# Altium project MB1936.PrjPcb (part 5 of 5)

## Sheet Power_PMIC.SchDoc: Power PMIC
size A3; Date: Not used; ApprovedBy: Not used; CheckedBy: Not used; Author: Not used; CompanyName: STMicroelectronics; DrawnBy: Not used; Engineer: Not used; Organization: Not used; Address1: Not used; Address2: Not used; Address3: Not used; Address4: Not used; DocumentNumber: Not used; Revision: Not used; SheetNumber: 4; SheetTotal: 18
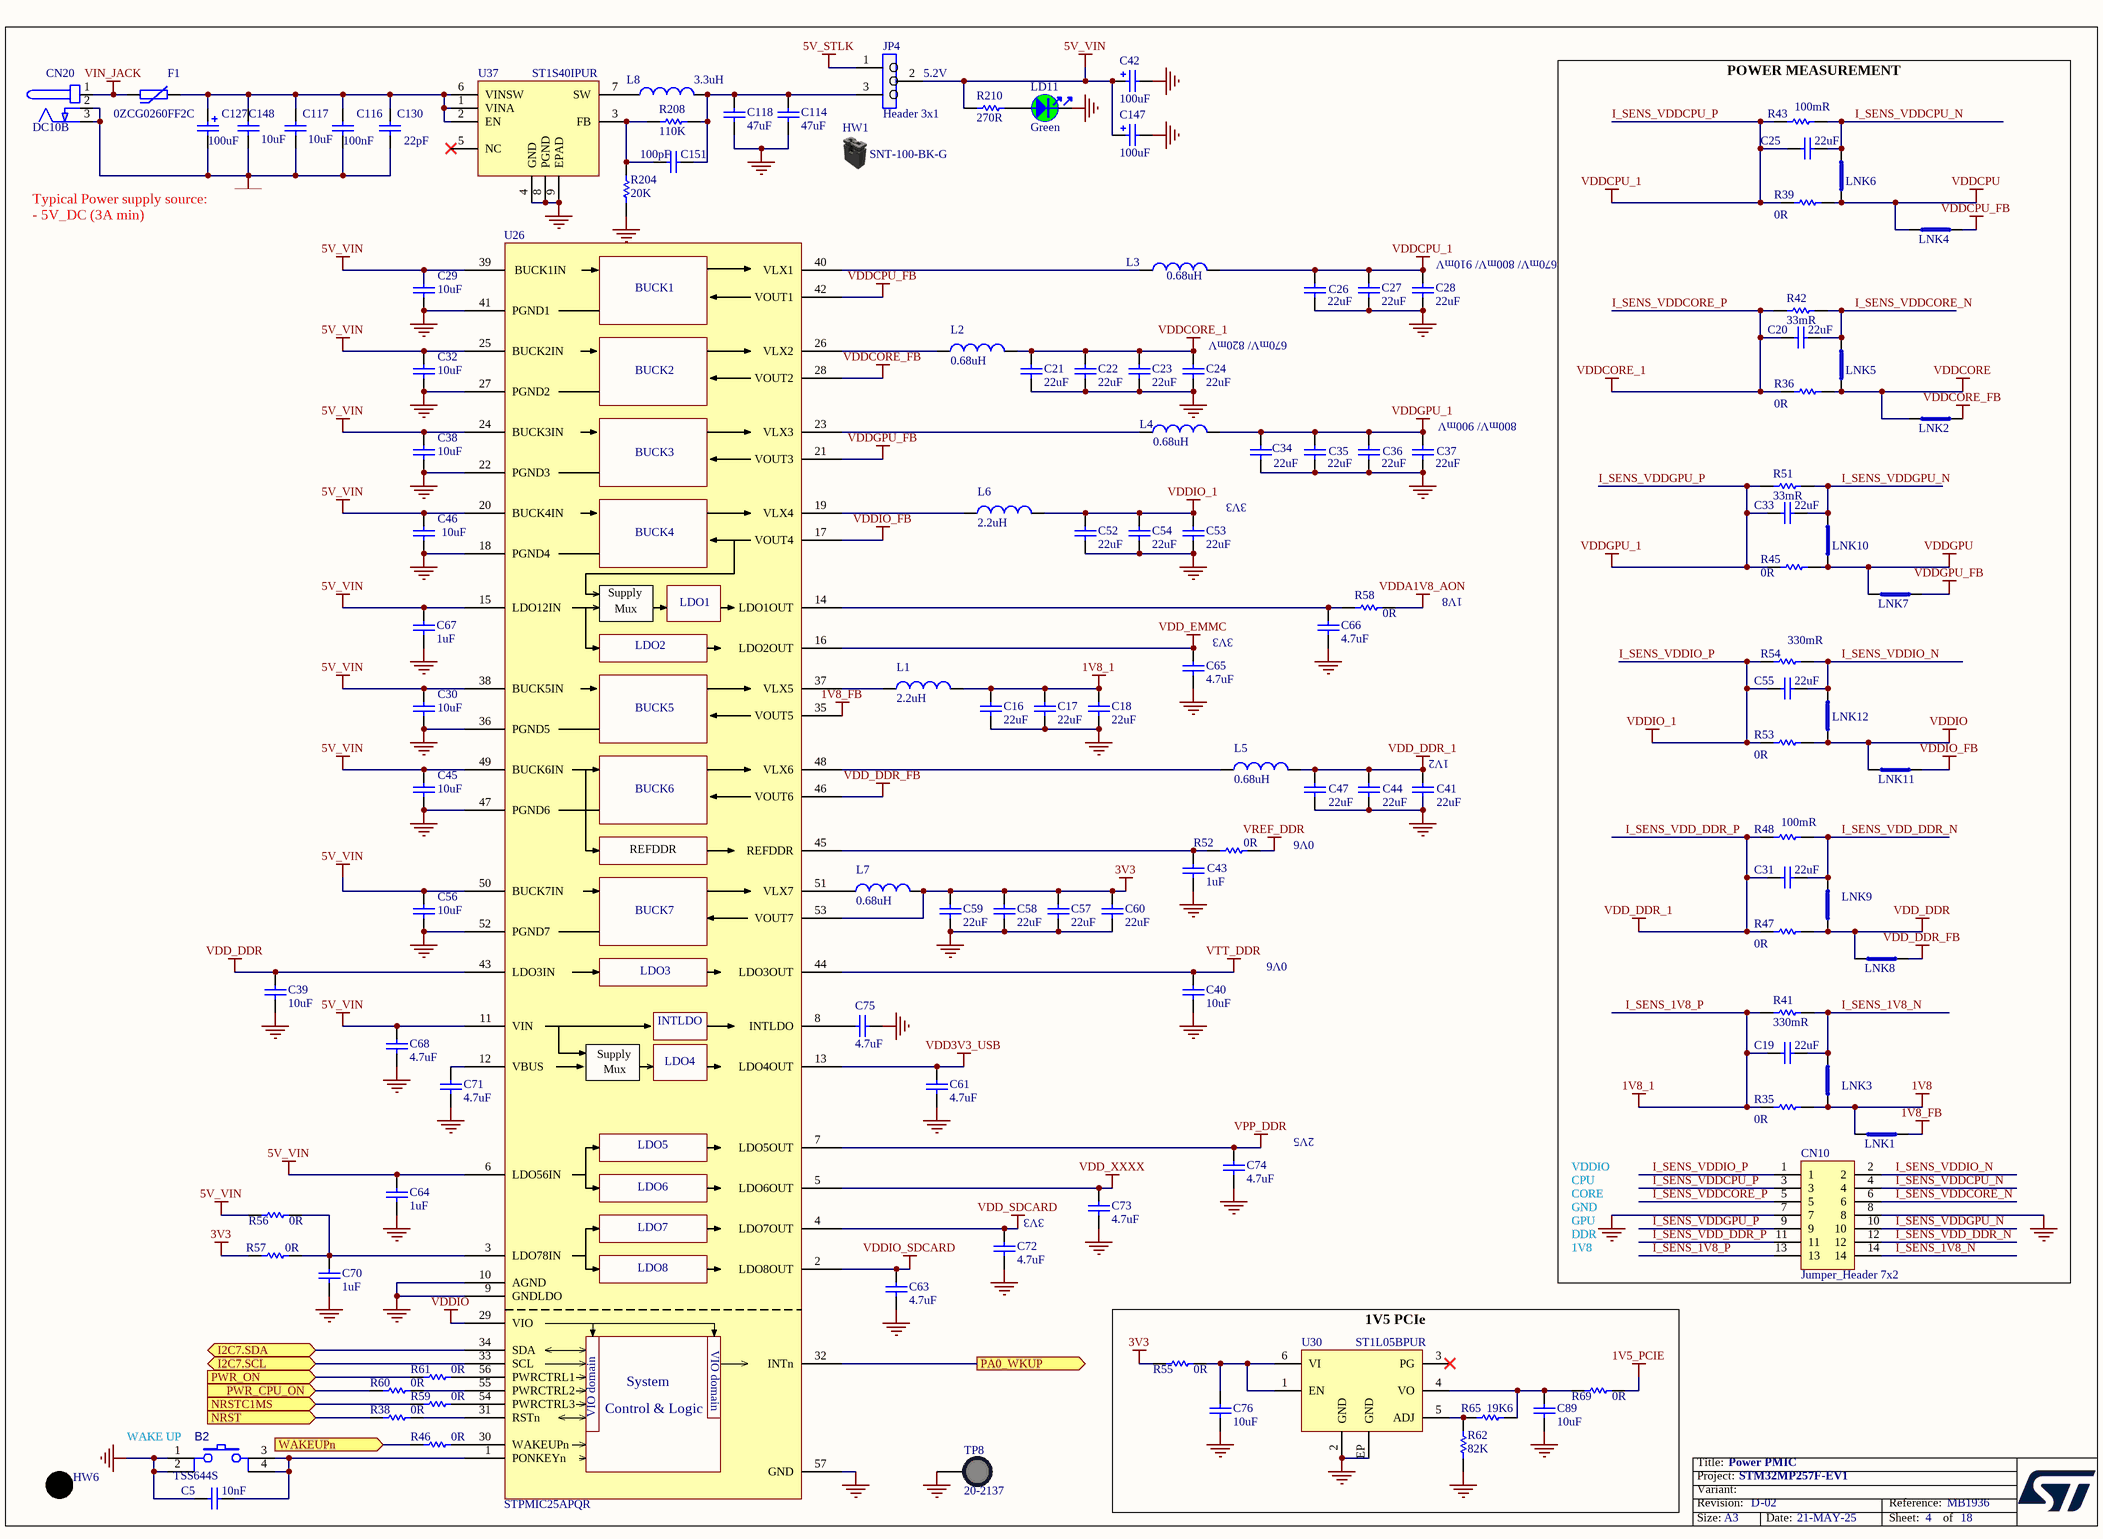
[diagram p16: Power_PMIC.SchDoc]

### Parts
B2  value TSS644S  [SWI_KNITTER_TSS644S]  (hidden comment: SW_PUSH_SMD)
C5  value 10nF  [C0402]  (hidden comment: Capacitor)
C16  value 22uF  [C0805]  (hidden comment: Capacitor)
C17  value 22uF  [C0805]  (hidden comment: Capacitor)
C18  value 22uF  [C0805]  (hidden comment: Capacitor)
C19  value 22uF  [C0603]  (hidden comment: Capacitor)
C20  value 22uF  [C0603]  (hidden comment: Capacitor)
C21  value 22uF  [C0603]  (hidden comment: Capacitor)
C22  value 22uF  [C0603]  (hidden comment: Capacitor)
C23  value 22uF  [C0603]  (hidden comment: Capacitor)
C24  value 22uF  [C0603]  (hidden comment: Capacitor)
C25  value 22uF  [C0603]  (hidden comment: Capacitor)
C26  value 22uF  [C0603]  (hidden comment: Capacitor)
C27  value 22uF  [C0603]  (hidden comment: Capacitor)
C28  value 22uF  [C0603]  (hidden comment: Capacitor)
C29  value 10uF  [C0603]  (hidden comment: Capacitor)
C30  value 10uF  [C0603]  (hidden comment: Capacitor)
C31  value 22uF  [C0603]  (hidden comment: Capacitor)
C32  value 10uF  [C0603]  (hidden comment: Capacitor)
C33  value 22uF  [C0603]  (hidden comment: Capacitor)
C34  value 22uF  [C0603]  (hidden comment: Capacitor)
C35  value 22uF  [C0603]  (hidden comment: Capacitor)
C36  value 22uF  [C0603]  (hidden comment: Capacitor)
C37  value 22uF  [C0603]  (hidden comment: Capacitor)
C38  value 10uF  [C0603]  (hidden comment: Capacitor)
C39  value 10uF  [C0402]  (hidden comment: Capacitor)
C40  value 10uF  [C0402]  (hidden comment: Capacitor)
C41  value 22uF  [C0603]  (hidden comment: Capacitor)
C42  value 100uF  [CPOL_TCJ-B_1210_H210]  (hidden comment: Cap_POL_TANA)
C43  value 1uF  [C0402]  (hidden comment: Capacitor)
C44  value 22uF  [C0603]  (hidden comment: Capacitor)
C45  value 10uF  [C0603]  (hidden comment: Capacitor)
C46  value 10uF  [C0603]  (hidden comment: Capacitor)
C47  value 22uF  [C0603]  (hidden comment: Capacitor)
C52  value 22uF  [C0805]  (hidden comment: Capacitor)
C53  value 22uF  [C0805]  (hidden comment: Capacitor)
C54  value 22uF  [C0805]  (hidden comment: Capacitor)
C55  value 22uF  [C0603]  (hidden comment: Capacitor)
C56  value 10uF  [C0603]  (hidden comment: Capacitor)
C57  value 22uF  [C0805]  (hidden comment: Capacitor)
C58  value 22uF  [C0805]  (hidden comment: Capacitor)
C59  value 22uF  [C0805]  (hidden comment: Capacitor)
C60  value 22uF  [C0805]  (hidden comment: Capacitor)
C61  value 4.7uF  [C0402]  (hidden comment: Capacitor)
C63  value 4.7uF  [C0402]  (hidden comment: Capacitor)
C64  value 1uF  [C0402]  (hidden comment: Capacitor)
C65  value 4.7uF  [C0402]  (hidden comment: Capacitor)
C66  value 4.7uF  [C0402]  (hidden comment: Capacitor)
C67  value 1uF  [C0402]  (hidden comment: Capacitor)
C68  value 4.7uF  [C0402]  (hidden comment: Capacitor)
C70  value 1uF  [C0402]  (hidden comment: Capacitor)
C71  value 4.7uF  [C0603]  (hidden comment: Capacitor)
C72  value 4.7uF  [C0402]  (hidden comment: Capacitor)
C73  value 4.7uF  [C0402]  (hidden comment: Capacitor)
C74  value 4.7uF  [C0402]  (hidden comment: Capacitor)
C75  value 4.7uF  [C0402]  (hidden comment: Capacitor)
C76  value 10uF  [C0603]  (hidden comment: Capacitor)
C89  value 10uF  [C0603]  (hidden comment: Capacitor)
C114  value 47uF  [C0805]  (hidden comment: Capacitor)
C116  value 100nF  [C0805_H0P85]  (hidden comment: Capacitor)
C117  value 10uF  [C0805]  (hidden comment: Capacitor)
C118  value 47uF  [C0805]  (hidden comment: Capacitor)
C127  value 100uF  [CPOL_WURTH_WCAP-ASLL_8X10P5]  (hidden comment: Cap_POL_TANA)
C130  value 22pF  [C0402]  (hidden comment: Capacitor)
C147  value 100uF  [CPOL_TCJ-B_1210_H210]  (hidden comment: Cap_POL_TANA)
C148  value 10uF  [C0805]  (hidden comment: Capacitor)
C151  value 100pF  [C0402]  (hidden comment: Capacitor)
CN10  value Jumper_Header 7x2  [CON_SAMTEC_TSW-107-07-X-D]  (hidden comment: Header 7x2)
CN20  DC10B  [CON_DC-POWER-SOCKET_CLIFF_FC68149_DC10B]
F1  0ZCG0260FF2C  [PTC_BEL-FUSE_1812_0ZCG0260FF2C]
HW1  value SNT-100-BK-G  (hidden comment: Shunt Black 2.54mm)  (mechanical)
HW6  SW-CAP-KTSC-62K  (value not drawn)  (mechanical)
JP4  value Header 3x1  [CON_SAMTEC_TSW-103-07-F-S]  (hidden comment: Jumper_Header 3x1)
L1  value 2.2uH  [IND_2016_MURATA_LQM2MPN2R2NG0]  (hidden comment: Inductor)
L2  value 0.68uH  [IND_2520_TOKO_DFE252012P]  (hidden comment: Inductor)
L3  value 0.68uH  [IND_2016_MURATA_LQM2MPN2R2NG0]  (hidden comment: Inductor)
L4  value 0.68uH  [IND_2520_TOKO_DFE252012P]  (hidden comment: Inductor)
L5  value 0.68uH  [IND_2016_MURATA_LQM2MPN2R2NG0]  (hidden comment: Inductor)
L6  value 2.2uH  [IND_2016_MURATA_LQM2MPN2R2NG0]  (hidden comment: Inductor)
L7  value 0.68uH  [IND_2016_MURATA_LQM2MPN2R2NG0]  (hidden comment: Inductor)
L8  value 3.3uH  [IND_5040_WURTH_74404054033]  (hidden comment: Inductor)
LD11  value Green  [LED_0603_OSRAM_LG-Q396-PS-35_GREEN_1A2K_H0P4]  (hidden comment: LED_green)
LNK1  link_200  [LINK200]  (value not drawn)  (no BOM)
LNK2  link_200  [LINK200]  (value not drawn)  (no BOM)
LNK3  link_200  [LINK200]  (value not drawn)  (no BOM)
LNK4  link_200  [LINK200]  (value not drawn)  (no BOM)
LNK5  link_200  [LINK200]  (value not drawn)  (no BOM)
LNK6  link_200  [LINK200]  (value not drawn)  (no BOM)
LNK7  link_200  [LINK200]  (value not drawn)  (no BOM)
LNK8  link_200  [LINK200]  (value not drawn)  (no BOM)
LNK9  link_200  [LINK200]  (value not drawn)  (no BOM)
LNK10  link_200  [LINK200]  (value not drawn)  (no BOM)
LNK11  link_200  [LINK200]  (value not drawn)  (no BOM)
LNK12  link_200  [LINK200]  (value not drawn)  (no BOM)
R35  value 0R  [R0603]  (hidden comment: Resistor)
R36  value 0R  [R0603]  (hidden comment: Resistor)
R38  value 0R  [R0402]
R39  value 0R  [R0603]  (hidden comment: Resistor)
R41  value 330mR  [R0603]  (hidden comment: Resistor)
R42  value 33mR  [R0603]  (hidden comment: Resistor)
R43  value 100mR  [R0603]  (hidden comment: Resistor)
R45  value 0R  [R0603]  (hidden comment: Resistor)
R46  value 0R  [R0402]
R47  value 0R  [R0603]  (hidden comment: Resistor)
R48  value 100mR  [R0603]  (hidden comment: Resistor)
R51  value 33mR  [R0603]  (hidden comment: Resistor)
R52  value 0R  [R0402]  (hidden comment: Resistor)
R53  value 0R  [R0603]  (hidden comment: Resistor)
R54  value 330mR  [R0603]  (hidden comment: Resistor)
R55  value 0R  [R0603]  (hidden comment: Resistor)
R56  value 0R  [R0603]  (hidden comment: Resistor)
R57  value 0R  [R0402]  (hidden comment: Resistor)
R58  value 0R  [R0603]  (hidden comment: Resistor)
R59  value 0R  [R0402]
R60  value 0R  [R0402]
R61  value 0R  [R0402]
R62  value 82K  [R0402]  (hidden comment: Resistor)
R65  value 19K6  [R0402]  (hidden comment: Resistor)
R69  value 0R  [R0603]  (hidden comment: Resistor)
R204  value 20K  [R0402]  (hidden comment: Resistor)
R208  value 110K  [R0402]  (hidden comment: Resistor)
R210  value 270R  [R0402]  (hidden comment: Resistor)
TP8  value 20-2137  [TP_PTH-1P02MM_TEST-TERMINAL_RS_101-2391_BLACK]  (hidden comment: Test_pin_conn_black)
U26  value STPMIC25APQR  [ICC_QFN56-EPAD_6P5X6P5_P040]  (hidden comment: STPMIC2)
U30  ST1L05BPUR  [ICC_DFN6-EPAD_3X3_P095]
U37  ST1S40IPUR  [ICC_VFQFPN8-EPAD_4X4_P080]

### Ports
I2C7.SCL (bidir), I2C7.SDA (bidir), NRST (in), NRSTC1MS (in), PA0_WKUP (out), PWR_CPU_ON (in), PWR_ON (in), WAKEUPn (in)

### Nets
1V5_PCIE: R69.2
1V8: LNK1.2 LNK3.2 R35.2
1V8_FB: LNK1.1 U26.35(VOUT5)
3V3: C57.2 C58.2 C59.2 C60.2 L7.2 R55.1 R57.1 U26.53(VOUT7)
5V_STLK: JP4.1
5V_VIN: C29.2 C30.2 C32.2 C38.2 C42.1 C45.2 C46.2 C56.2 C64.2 C67.2 C68.2 C147.1 JP4.2 R56.1 R210.2 U26.6(LDO56IN) U26.11(VIN) U26.15(LDO12IN) U26.20(BUCK4IN) U26.24(BUCK3IN) U26.25(BUCK2IN) U26.38(BUCK5IN) U26.39(BUCK1IN) U26.49(BUCK6IN) U26.50(BUCK7IN)
GND: B2.1 B2.2 C5.1 C16.1 C17.1 C18.1 C21.1 C22.1 C23.1 C24.1 C26.1 C27.1 C28.1 C29.1 C30.1 C32.1 C34.1 C35.1 C36.1 C37.1 C38.1 C39.1 C40.1 C41.1 C42.2 C43.2 C44.1 C45.1 C46.1 C47.1 C52.1 C53.1 C54.1 C56.1 C57.1 C58.1 C59.1 C60.1 C61.1 C63.2 C64.1 C65.2 C66.1 C67.1 C68.1 C70.1 C71.1 C72.2 C73.2 C74.2 C75.2 C76.1 C89.1 C114.1 C116.1 C117.1 C118.1 C127.2 C130.1 C147.2 C148.1 CN10.7 CN10.8 CN20.2 CN20.3 LD11.2 R62.1 R204.1 TP8.1 U26.9(GNDLDO) U26.10(AGND) U26.18(PGND4) U26.22(PGND3) U26.27(PGND2) U26.36(PGND5) U26.41(PGND1) U26.47(PGND6) U26.52(PGND7) U26.57(GND) U30.2(GND) U30.EP(GND) U37.4(GND) U37.8(PGND) U37.9(EPAD)
I_SENS_1V8_P: C16.2 C17.2 C18.2 C19.2 CN10.13 L1.2 R35.1 R41.1  [also labelled 1V8_1]
I_SENS_VDD_DDR_P: C31.2 C41.2 C44.2 C47.2 CN10.11 L5.2 R47.1 R48.1  [also labelled VDD_DDR_1]
I_SENS_VDDCORE_P: C20.2 C21.2 C22.2 C23.2 C24.2 CN10.5 L2.2 R36.1 R42.1  [also labelled VDDCORE_1]
I_SENS_VDDCPU_P: C25.2 C26.2 C27.2 C28.2 CN10.3 L3.2 R39.1 R43.1  [also labelled VDDCPU_1]
I_SENS_VDDGPU_P: C33.2 C34.2 C35.2 C36.2 C37.2 CN10.9 L4.2 R45.1 R51.1  [also labelled VDDGPU_1]
I_SENS_VDDIO_P: C52.2 C53.2 C54.2 C55.2 CN10.1 L6.2 R53.1 R54.1  [also labelled VDDIO_1]
VDD3V3_USB: C61.2 U26.13(LDO4OUT)
VDD_DDR: C39.2 LNK8.2 LNK9.2 R47.2 U26.43(LDO3IN)
VDD_DDR_FB: LNK8.1 U26.46(VOUT6)
VDD_EMMC: C65.1 U26.16(LDO2OUT)
VDD_SDCARD: C72.1 U26.4(LDO7OUT)
VDD_XXXX: C73.1 U26.5(LDO6OUT)
VDDA1V8_AON: R58.2
VDDCORE: LNK2.2 LNK5.1 R36.2
VDDCORE_FB: LNK2.1 U26.28(VOUT2)
VDDCPU: LNK4.1 LNK6.1 R39.2
VDDCPU_FB: LNK4.2 U26.42(VOUT1)
VDDGPU: LNK7.2 LNK10.1 R45.2
VDDGPU_FB: LNK7.1 U26.21(VOUT3)
VDDIO: LNK11.2 LNK12.2 R53.2 U26.29(VIO)
VDDIO_FB: LNK11.1 U26.17(VOUT4)
VDDIO_SDCARD: C63.1 U26.2(LDO8OUT)
VIN_JACK: CN20.1 F1.1
VPP_DDR: C74.1 U26.7(LDO5OUT)
VREF_DDR: R52.2
VTT_DDR: C40.2 U26.44(LDO3OUT)
I2C7.SCL: U26.33(SCL) ; port I2C7.SCL
I2C7.SDA: U26.34(SDA) ; port I2C7.SDA
I_SENS_1V8_N: C19.1 CN10.14 LNK3.1 R41.2
I_SENS_VDD_DDR_N: C31.1 CN10.12 LNK9.1 R48.2
I_SENS_VDDCORE_N: C20.1 CN10.6 LNK5.2 R42.2
I_SENS_VDDCPU_N: C25.1 CN10.4 LNK6.2 R43.2
I_SENS_VDDGPU_N: C33.1 CN10.10 LNK10.2 R51.2
I_SENS_VDDIO_N: C55.1 CN10.2 LNK12.1 R54.2
NRST: R38.1 ; port NRST
NRSTC1MS: R59.1 ; port NRSTC1MS
PA0_WKUP: U26.32(INTn) ; port PA0_WKUP
PWR_CPU_ON: R60.1 ; port PWR_CPU_ON
PWR_ON: R61.1 ; port PWR_ON
WAKEUPn: R46.1 ; port WAKEUPn
NetB2_3: B2.3 B2.4 C5.2 U26.1(PONKEYn)
NetC43_1: C43.1 R52.1 U26.45(REFDDR)
NetC66_2: C66.2 R58.1 U26.14(LDO1OUT)
NetC70_2: C70.2 R56.2 R57.2 U26.3(LDO78IN)
NetC71_2: C71.2 U26.12(VBUS)
NetC75_1: C75.1 U26.8(INTLDO)
NetC76_2: C76.2 R55.2 U30.1(EN) U30.6(VI)
NetC89_2: C89.2 R65.2 R69.1 U30.4(VO)
NetC114_2: C114.2 C118.2 C151.1 JP4.3 L8.2 R208.1
NetC116_2: C116.2 C117.2 C127.1 C130.2 C148.2 F1.2 U37.1(VINA) U37.2(EN) U37.6(VINSW)
NetC151_2: C151.2 R204.2 R208.2 U37.3(FB)
NetL1_1: L1.1 U26.37(VLX5)
NetL2_1: L2.1 U26.26(VLX2)
NetL3_1: L3.1 U26.40(VLX1)
NetL4_1: L4.1 U26.23(VLX3)
NetL5_1: L5.1 U26.48(VLX6)
NetL6_1: L6.1 U26.19(VLX4)
NetL7_1: L7.1 U26.51(VLX7)
NetL8_1: L8.1 U37.7(SW)
NetLD11_1: LD11.1 R210.1
NetR38_2: R38.2 U26.31(RSTn)
NetR46_2: R46.2 U26.30(WAKEUPn)
NetR59_2: R59.2 U26.54(PWRCTRL3)
NetR60_2: R60.2 U26.55(PWRCTRL2)
NetR61_2: R61.2 U26.56(PWRCTRL1)
NetR62_2: R62.2 R65.1 U30.5(ADJ)

Not connected (* = marked no-connect by the designer): U30 3(PG)*; U37 5(NC)*

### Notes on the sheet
- 5.2V
- Typical Power supply source:
  - 5V_DC (3A min)
- (near C28) 670mV/ 800mV/ 910mV
- (near C24) 670mV/ 820mV
- (near C37) 800mV/ 900mV
- 3V3
- 1V8
- (near C65) 3V3
- (near C41) 1V2
- 0V6
- 2V5
- (near C72) 3V3
- VDDIO
- CPU
- GND
- CORE
- POWER MEASUREMENT
- DDR
- GPU
- (near B2) WAKE UP
- 1V5 PCIe

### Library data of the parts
B2 = MCD-02417: Push Button, NO, 0.05A, 12V, 2.6N, SMD, 9.0x6.2mm, T=7.3mm, changeable caps KTSC-6xx; Part_Type: Misc; Manufacturer: KNITTER-SWITCH; Part_Preference: Recommended; Manufacturer_HQ_COO: Unknown; Component_Country_Of_Origin: China; ShowFields: YES; ID: 4523
C5 = MCD-02198: Capacitor, MLCC, 10nF, 50V, X7R, +/-10%, 0402, T=0.5mm; Manufacturer_Part_Number: CC0402KRX7R9BB103; Manufacturer: YAGEO; Part_Preference: Recommended; Order_Code_RS: 6169644; Component_Country_Of_Origin: China; ShowFields: YES; ID: 4298
C16-C18 C52-C54 C57-C60 = MCD-03139: Capacitor, MLCC, 22uF, 10V, X5R, +/-20%, 0805, T=1,25mm; Part_Preference: Recommended; Manufacturer: MURATA; Manufacturer_Part_Number: GRM21BR61A226ME51; ShowFields: YES; ID: 5255; Component_Country_Of_Origin: China, Japan
C19 C20 C22-C26 C31 C33-C37 C41 C44 C47 C55 = MCD-00100: Capacitor, MLCC, 22uF, 6V3, X5R, +/-20%, 0603, T=0,8mm; Manufacturer_Part_Number: GRM188R60J226MEA0; Manufacturer: MURATA; Part_Preference: Recommended; Partial_Alternate_Internal_Part_Number: MCD-04184; Component_Country_Of_Origin: Japan°°; ID: 2766; ShowFields: YES
C21 C27 C28 = MCD-00100: Capacitor, MLCC, 22uF, 6V3, X5R, +/-20%, 0603, T=0,8mm; Part_Preference: Recommended; Manufacturer: MURATA; Manufacturer_Part_Number: GRM188R60J226MEA0; Partial_Alternate_Internal_Part_Number: MCD-04184; Component_Country_Of_Origin: Japan°°; ID: 2766; ShowFields: YES
C29 C30 C32 C38 C45 C46 C56 = MCD-00099: Capacitor, MLCC, 10uF, 10V, X5R, +/-10%, 0603, T=0,8mm; Manufacturer_Part_Number: GRM188R61A106KE69; Manufacturer: MURATA; Part_Preference: Recommended; Partial_Alternate_Internal_Part_Number: MCD-03152; Order_Code_RS: 2494233; Component_Country_Of_Origin: Japan°°; ID: 2770; ShowFields: YES
C39 C40 = MCD-03140: Capacitor, MLCC, 10uF, 6.3V, X5R, +/-20%, 0402, T=0.5mm; Part_Preference: Recommended; Manufacturer: MURATA; Manufacturer_Part_Number: GRM155R60J106ME05; ShowFields: YES; ID: 5256; Component_Country_Of_Origin: China, Japan
C42 C147 = MCD-01796: Capacitor, Tantalum, 100uF, 6V3, 40mR, +/-20%,  Type_B (3528 metric), T=1.9mm; Part_Preference: Recommended; Manufacturer: AVX; Manufacturer_Part_Number: TCJB107M006R0040; Partial_Alternate_Internal_Part_Number: MCD-04209; Component_Country_Of_Origin: Czech Republic; ShowFields: YES; ID: 3896
C43 = MCD-01722: Capacitor, MLCC, 1uF, 10V, X5R, +/-10%, 0402, T=0.5mm; Part_Preference: Recommended; Manufacturer: YAGEO; Manufacturer_Part_Number: CC0402KRX5R6BB105; Component_Country_Of_Origin: China; ID: 3822; ShowFields: YES
C61 C63 C65 C66 C68 C72-C75 = MCD-01356: Capacitor, MLCC, 4.7uF, 6V3, X5R, +/-20%, 0402, T=0.5mm; Manufacturer_Part_Number: GRM155R60J475ME47; Manufacturer: MURATA; Part_Preference: Recommended; Partial_Alternate_Internal_Part_Number: MCD-04455; Order_Code_RS: 814-5230; Component_Country_Of_Origin: Japan°°; ShowFields: YES; ID: 3456
C64 C67 C70 = MCD-00095: Capacitor, MLCC, 1uF, 25V, X5R, +/-10%, 0402, T=0.5mm; Part_Preference: Recommended; Manufacturer: MURATA; Manufacturer_Part_Number: GRM155R61E105KA12; Partial_Alternate_Internal_Part_Number: MCD-04188; Order_Code_RS: 2218855; Component_Country_Of_Origin: Japan°°; ShowFields: YES; ID: 2772
C71 = MCD-00097: Capacitor, MLCC, 4.7uF, 16V, X5R, +/-20%, 0603, T=0.8mm; Part_Preference: Recommended; Manufacturer: MURATA; Manufacturer_Part_Number: GRM188R61C475KE11; Component_Country_Of_Origin: Japan°°; ShowFields: YES; ID: 2767
C76 C89 = MCD-00099: Capacitor, MLCC, 10uF, 10V, X5R, +/-10%, 0603, T=0.8mm; Part_Preference: Recommended; Manufacturer: MURATA; Manufacturer_Part_Number: GRM188R61A106KE69; Partial_Alternate_Internal_Part_Number: MCD-03152; Order_Code_RS: 2494233; Component_Country_Of_Origin: Japan°°; ShowFields: YES; ID: 2770
C114 C118 = MCD-00204: Capacitor, MLCC, 47uF, 10V, X5R, +/-20%, 0805, T=1,25mm; Part_Preference: Recommended; Manufacturer: MURATA; Manufacturer_Part_Number: GRM21BR61A476ME15; Component_Country_Of_Origin: Japan°°; ID: 2664; ShowFields: YES
C116 = MCD-01525: Capacitor, MLCC, 100nF, 50V, X7R, 10%, 0805, T=0,85mm; BMS_Part_Number: 9142249; Part_Preference: Recommended; Manufacturer: YAGEO; Manufacturer_Part_Number: CC0805KRX7R9BB104; Order_Code_RS: 669-8842; Component_Country_Of_Origin: China; ID: 3625; ShowFields: YES
C117 C148 = MCD-00014: Capacitor, MLCC, 10uF, 25V, X5R, +/-10%, 0805, T=0,85mm; Part_Preference: Recommended; Manufacturer: YAGEO; Manufacturer_Part_Number: CC0805KRX5R8BB106; Full_Alternate_Internal_Part_Number: MCD-02385; Partial_Alternate_Internal_Part_Number: MCD-03053; Component_Country_Of_Origin: China; ID: 2468; ShowFields: YES
C127 = MCD-01683: Capacitor,Electrolytic,100uF,35V, 20%, SMT, D=8mm, T=10.5mm; Part_Preference: Recommended; Manufacturer: WURTH ELEKTRONIK; Manufacturer_Part_Number: 865060553006; Order_Code_RS: 839-5753; Component_Country_Of_Origin: Unknown; ID: 3783; ShowFields: YES
C130 = MCD-01995: Capacitor, MLCC, 22pF, 50V, C0G, 5%, 0402, T=0,5mm; Part_Preference: Recommended; Manufacturer: TDK; Manufacturer_Part_Number: C1005NP01H220J050BA; Partial_Alternate_Internal_Part_Number: MCD-04601; Component_Country_Of_Origin: Unknown; ID: 4095; ShowFields: YES
C151 = MCD-00205: Capacitor,MLCC,100pF,50V,NPO,+/-5%,0402,T=0,5mm; Manufacturer_Part_Number: CC0402JRNPO9BN101; Manufacturer: YAGEO; Part_Preference: Recommended; Fitted: YES; Component_Country_Of_Origin: China; ID: 2658
CN10 = MCD-02123: Header, 7x2, 2,54mm, VR, TH, Height 5.84mm/2.54mm; Part_Type: Connector; Part_Preference: Recommended; Manufacturer: SAMTEC; Manufacturer_Part_Number: TSW-107-07-G-D; Partial_Alternate_Internal_Part_Number: MCD-04207, MCD-04247; Component_Country_Of_Origin: China, Costa Rica, Malaysia, USA, Vietnam; ID: 4223; ShowFields: YES
CN20 = MCD-00173: DC-Power-Jack, 2.5mm, 5A, RA, TH; BMS_Part_Number: 9087803; Part_Preference: Recommended; Part_Type: Connector; Manufacturer: CLIFF; Partial_Alternate_Internal_Part_Number: MCD-04205, MCD-04592; Value: Jack_DC-Power_DC10B; Component_Country_Of_Origin: Taiwan; ID: 2695; ShowFields: YES
F1 = MCD-00624: SMD, PTC resettable fuse, IH:2.6A, IT:5A, Vdc_max:8V, Rmax:47mohm, BELFUSE; Part_Preference: Recommended; Part_Type: Misc; Component_Country_Of_Origin: Unknown; ID: 3118; ShowFields: YES
HW1 = MCD-00043: SHUNT 2.54mm BLACK; Part_Type: Misc; Part_Preference: Recommended; Manufacturer: SAMTEC; Manufacturer_HQ_COO: Unknown; Partial_Alternate_Internal_Part_Number: MCD-01849, MCD-01864, MCD-02388, MCD-03991, MCD-04284, MCD-04580; Component_Country_Of_Origin: China, Costa Rica, Malaysia, USA, Vietnam; ShowFields: YES; ID: 2551; Alternate_EMS: A; Order_Code_RS: 158-7784
HW6 = MCD-02420: Black round cap for TSS6x series; Part_Type: Mechanical; Part_Preference: Recommended; Manufacturer: KNITTER-SWITCH; Manufacturer_HQ_COO: Unknown; Partial_Alternate_Internal_Part_Number: MCD-02526; Component_Country_Of_Origin: China; ID: 4526; ShowFields: YES; Alternate_EMS: M
JP4 = MCD-00111: Header, 3x1, 2.54mm, VR, TH, T=5.84mm/2.54mm; Part_Type: Connector; Part_Preference: Recommended; Manufacturer: SAMTEC; Manufacturer_Part_Number: TSW-103-07-F-S; Partial_Alternate_Internal_Part_Number: MCD-04583; Order_Code_RS: 161-2248; Component_Country_Of_Origin: China, Costa Rica, Malaysia, USA, Vietnam; ShowFields: YES; ID: 2760
L1 L6 = MCD-03143: Inductor, 2.2uH, +/-20%, Itemp= 1700mA, Isat= 2400mA, 0R140, 0806, T=1mm; Part_Preference: Recommended; Manufacturer: MURATA; Manufacturer_Part_Number: DFE201610E-2R2M=P2; ShowFields: YES; ID: 5259; Component_Country_Of_Origin: Vietnam
L2 L4 = MCD-03142: Inductor, 0.68uH, +/-20%, Itemp= 3900mA, Isat= 5400mA, 0R031, 1008, T=1.2mm; Part_Preference: Recommended; Manufacturer: MURATA; Manufacturer_Part_Number: DFE252012F-R68M=P2; ShowFields: YES; ID: 5258; Component_Country_Of_Origin: Vietnam
L3 L5 L7 = MCD-03141: Inductor, 0.68uH, +/-20%, Itemp= 3100mA, Isat= 4300mA, 0R043, 0806, T=1mm; Part_Preference: Recommended; Manufacturer: MURATA; Manufacturer_Part_Number: DFE201610E-R68M=P2; ShowFields: YES; ID: 5257; Component_Country_Of_Origin: Vietnam
L8 = MCD-02220: Fixed Inductors WE-LQS 5040 3.3uH 3.4A 24mOhm; Part_Preference: Recommended; Manufacturer: WURTH ELEKTRONIK; Manufacturer_Part_Number: 74404054033; Order_Code_RS: 814-2571; Component_Country_Of_Origin: Unknown; ID: 4320; ShowFields: YES
LD11 = MCD-02901: LED, Green, 2V, 20mA, 0603; Part_Type: Display; Part_Preference: Recommended; Manufacturer: EVERLIGHT; Manufacturer_Part_Number: 19-217/G7C-AN1P2/6T; Partial_Alternate_Internal_Part_Number: MCD-02400, MCD-00588; Component_Country_Of_Origin: China; ShowFields: YES; ID: 5017
LNK1-LNK12 = link_200: link 0.2mm
R35 R36 R39 R45 R47 R53 = MCD-00181: Resistor,0R,0603,ULO; Manufacturer_Part_Number: PMR03EZPJ000; Manufacturer: ROHM SEMICONDUCTOR; Part_Preference: Recommended; Provided_By: SUBCO; Component_Country_Of_Origin: Philippines, Thailand°°; ID: 2691; ShowFields: YES
R38 R46 R59-R61 = MCD-00052: Resistor,0R,0402,5%,1/16W; Manufacturer_Part_Number: RC0402JR-070RL; Manufacturer: YAGEO; Part_Preference: Recommended; ECCN_US: EAR99; ECCN_EU: NEC; Provided_By: SUBCO; Initial_Board_Reference: mb1274; Order_Code_RS: 9232516RL; Component_Country_Of_Origin: China; ID: 2540; ShowFields: YES
R41 R54 = MCD-03197: Resistor, 330mR, 0603, +/-1%, 1/5W; Part_Preference: Recommended; Manufacturer: YAGEO; Manufacturer_Part_Number: PT0603FR-7W0R33L; Partial_Alternate_Internal_Part_Number: MCD-04231; ShowFields: YES; ID: 5313; Component_Country_Of_Origin: Taiwan
R42 R51 = MCD-03229: Resistor, 33mR, 0603, +/-1%, 1/4W; Part_Preference: Recommended; Manufacturer: PANASONIC; Manufacturer_Part_Number: ERJ-3BWFR033V; ShowFields: YES; ID: 5345
R43 R48 = MCD-02234: Resistor,100moHm,0603,1%,1/3W; Part_Preference: Recommended; Manufacturer: PANASONIC; Manufacturer_Part_Number: ERJ-3BWFR100V; Order_Code_RS: 763-8731; Component_Country_Of_Origin: Japan; ID: 4334; ShowFields: YES
R52 R57 = MCD-00052: Resistor,0R,0402,5%,1/16W; Manufacturer_Part_Number: RC0402JR-070RL; Manufacturer: YAGEO; Part_Preference: Recommended; Order_Code_RS: 9232516RL; Component_Country_Of_Origin: China; ID: 2540; ShowFields: YES
R55 R56 R69 = MCD-00056: Resistor,0R,0603,5%,1/10W; Manufacturer_Part_Number: RC0603JR-070RL; Manufacturer: YAGEO; Part_Preference: Recommended; Order_Code_RS: 9233130RL; Component_Country_Of_Origin: China; ID: 2536; ShowFields: YES
R58 = MCD-00181: Resistor, 0R, 0603, +/- 0.5mR, 1/4W; Part_Preference: Recommended; Manufacturer: ROHM SEMICONDUCTOR; Manufacturer_Part_Number: PMR03EZPJ000; Component_Country_Of_Origin: Philippines, Thailand°°; ID: 2691; ShowFields: YES
R62 = MCD-00531: Resistor, 82K, 0402, +/-1%, 1/16W; Part_Preference: Recommended; Manufacturer: YAGEO; Manufacturer_Part_Number: RC0402FR-0782KL; Component_Country_Of_Origin: China; ShowFields: YES; ID: 3207
R65 = MCD-00344: Resistor, 19K6, 0402, +/-1%, 1/16W; Part_Preference: Recommended; Manufacturer: YAGEO; Manufacturer_Part_Number: RC0402FR-0719K6L; Component_Country_Of_Origin: China; ShowFields: YES; ID: 2937
R204 = MCD-00421: Resistor,20K,0402,1%,1/16W; Part_Preference: Recommended; Manufacturer: YAGEO; Manufacturer_Part_Number: RC0402FR-0720KL; Component_Country_Of_Origin: China; ID: 2858; ShowFields: YES
R208 = MCD-00367: Resistor,110K,0402,1%,1/16W; Manufacturer_Part_Number: RC0402FR-07110KL; Manufacturer: YAGEO; Part_Preference: Recommended; Component_Country_Of_Origin: China; ID: 2912; ShowFields: YES
R210 = MCD-00441: Resistor,270R,0402,1%,1/16W; Manufacturer_Part_Number: RC0402FR-07270RL; Manufacturer: YAGEO; Part_Preference: Recommended; Provided_By: SUBCO; ECCN_US: EAR99; ECCN_EU: NEC; Component_Country_Of_Origin: China; ID: 2838; ShowFields: YES
TP8 = MCD-00713: Vero Technologies 1.02mm Black Terminal Post; Part_Type: Misc; Part_Preference: Recommended; Manufacturer_HQ_COO: Unknown; Partial_Alternate_Internal_Part_Number: MCD-04206, MCD-04594; Order_Code_RS: 101-2391; Component_Country_Of_Origin: UK; ID: 3032; ShowFields: YES
U26 = MCD-03000: Part_Type: IC; Part_Preference: Recommended; Manufacturer: STMICROELECTRONICS; Component_Country_Of_Origin: Unknown; ShowFields: YES; ID: 5116
U30 = MCD-00581: LDO Linear Voltage Regulator IC Positive Adjustable 1 Output Adjustable 1.3A 6-DFN (3x3); BMS_Part_Number: 9176239; Part_Preference: Recommended; Manufacturer: STMICROELECTRONICS; Manufacturer_HQ_COO: EU; Component_Country_Of_Origin: Malaysia; ShowFields: YES; ID: 3163; Order_Code_RS: 188-9209
U37 = MCD-02219: 3 A DC step-down switching regulator; Part_Preference: Recommended; Part_Type: IC; Manufacturer: STMICROELECTRONICS; Manufacturer_HQ_COO: EU; Component_Country_Of_Origin: Malaysia; ID: 4319; ShowFields: YES

## Sheet Expansion _&_mikroBUS_Connectors.SchDoc: EXPANSION_&_mikroBUS_ Connectors
size A3; CompanyName: STMicroelectronics; Organization: Microcontrollers Division; Address1: 12, Rue Jules HOROWITZ; Address2: 38019 Grenoble; Address3: FRANCE; Revision: A-01; SheetNumber: 16; SheetTotal: 18
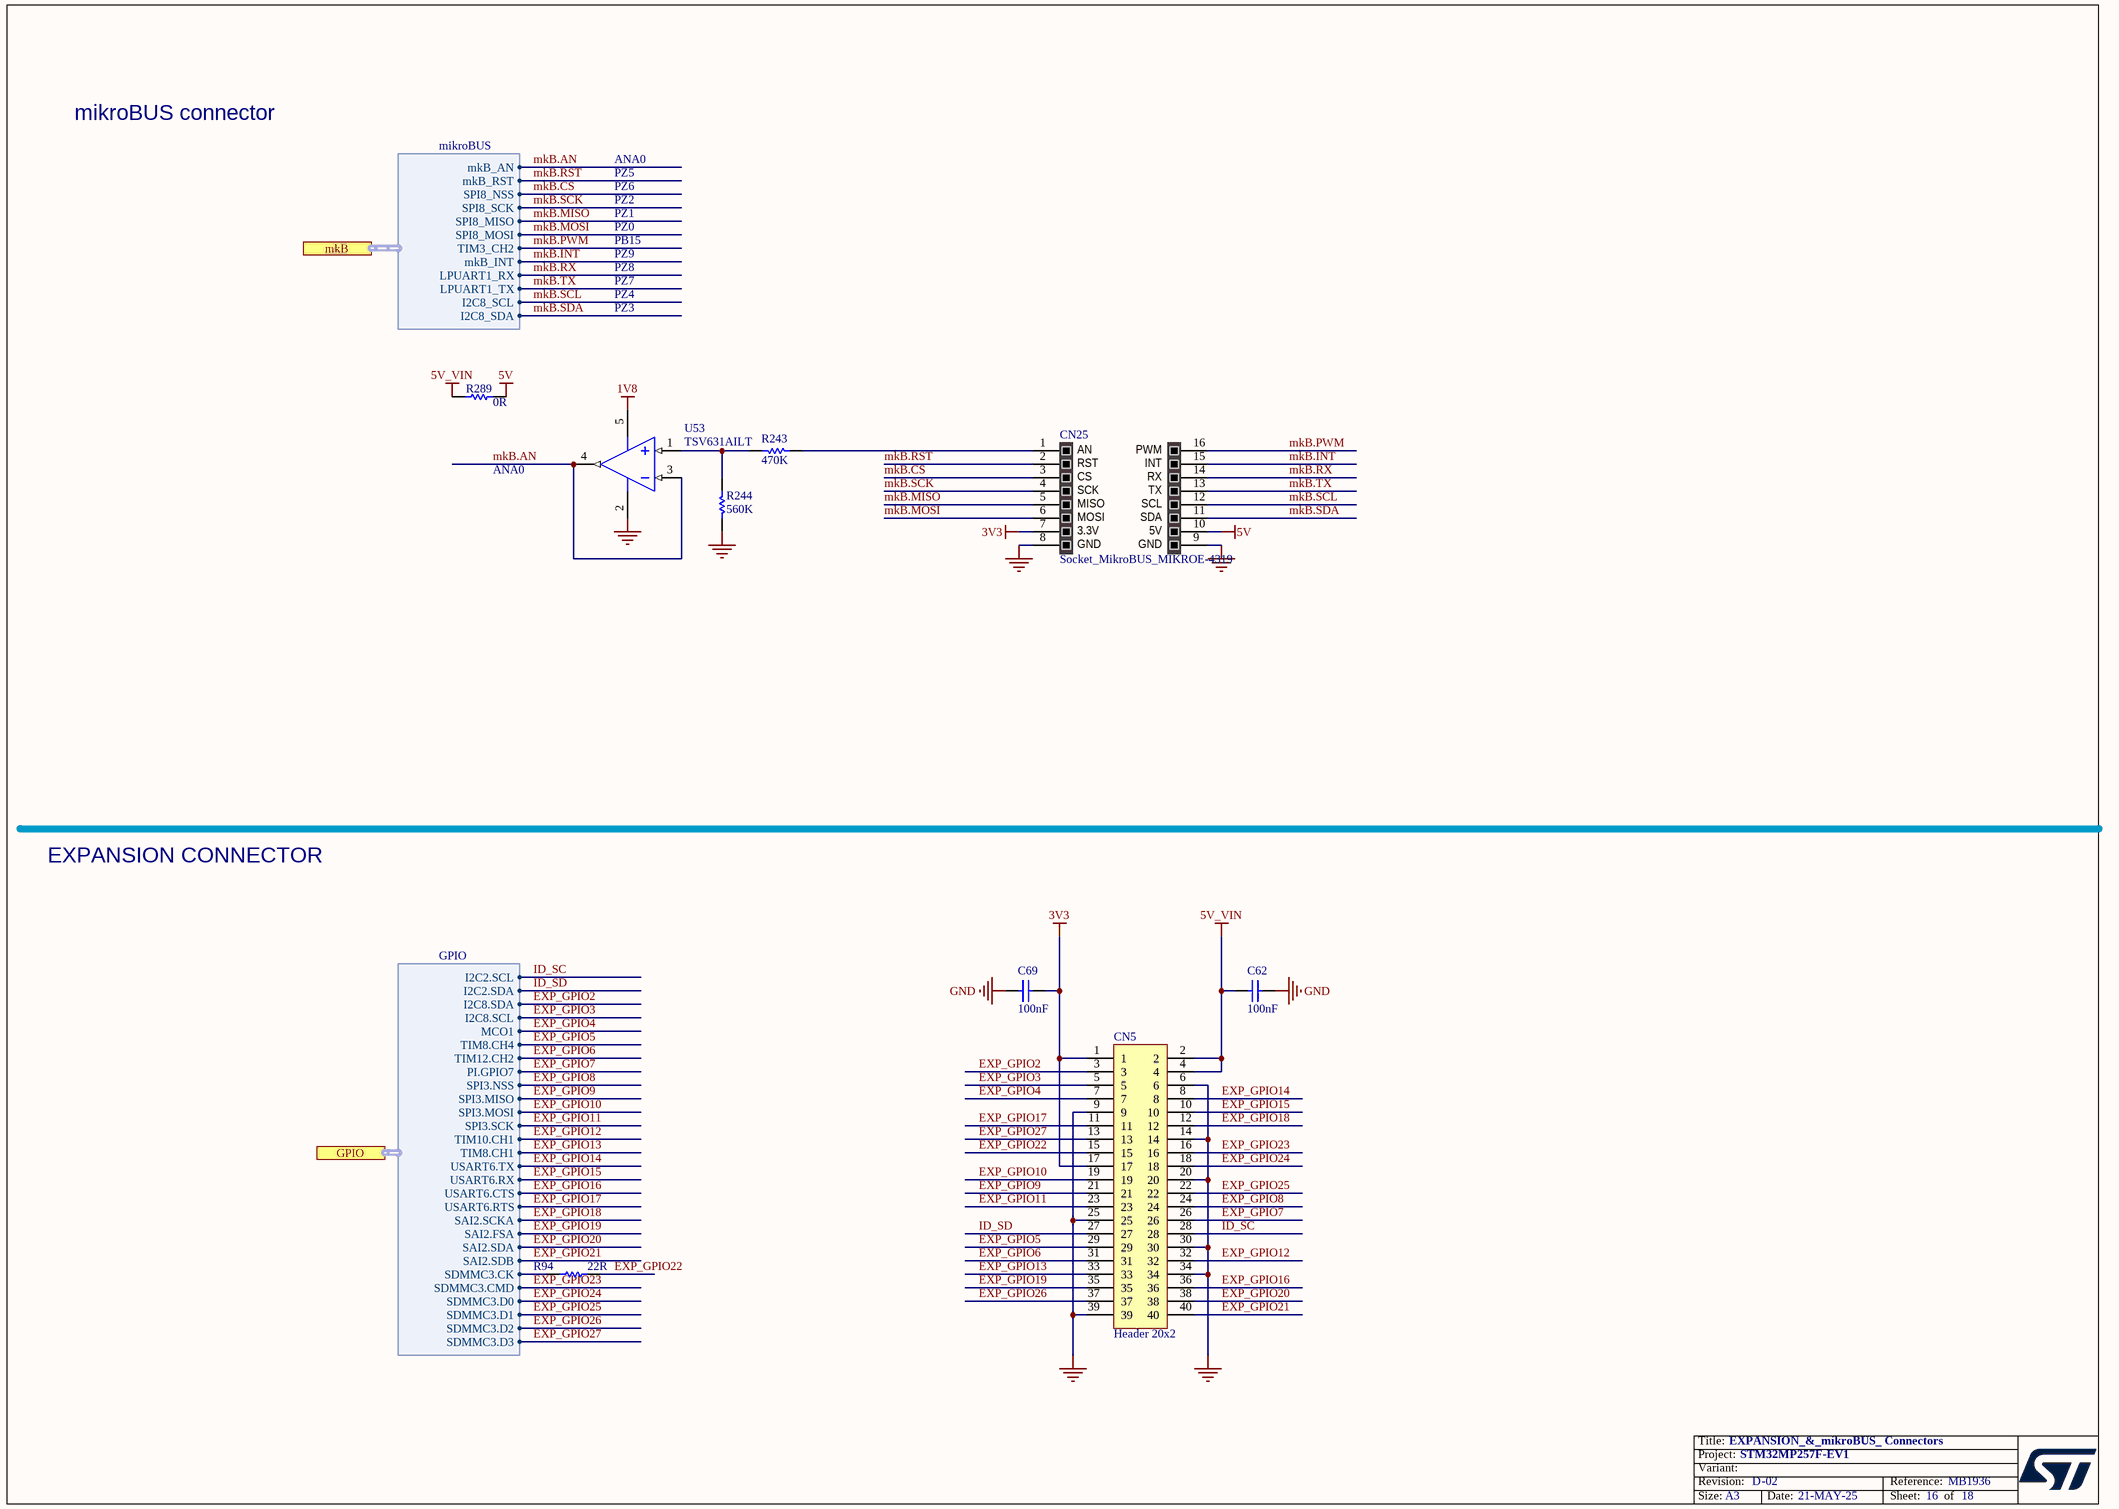
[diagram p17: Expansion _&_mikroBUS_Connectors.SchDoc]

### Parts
C62  value 100nF  [C0402]  (hidden comment: Capacitor)
C69  value 100nF  [C0402]  (hidden comment: Capacitor)
CN5  Header 20x2  [CON_SAMTEC_TSW-120-07-G-D]
CN25  value Socket_MikroBUS_MIKROE-4319  [SOCKET_MIKROBUS_MIKROE-4319_SMD_P254]  (hidden comment: MIKROE-4319)
R94  value 22R  [R0201_H0P23]  (hidden comment: Resistor)
R243  value 470K  [R0402]  (hidden comment: Resistor)
R244  value 560K  [R0402]  (hidden comment: Resistor)
R289  value 0R  [R0402]
U53  TSV631AILT  [AOP_SOT23-5L_H1P45]

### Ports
GPIO (harness GPIO), mkB (harness mikroBUS)

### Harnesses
GPIO: I2C2.SCL, I2C2.SDA, I2C8.SDA, MCO1, TIM8.CH4, TIM12.CH2, PI.GPIO7, SPI3.NSS, SPI3.MISO, SPI3.MOSI, SPI3.SCK, TIM10.CH1, TIM8.CH1, USART6.TX, USART6.RX, USART6.CTS, USART6.RTS, SDMMC3.CK, SDMMC3.CMD, SDMMC3.D0, SDMMC3.D1, SDMMC3.D2, SDMMC3.D3, I2C8.SCL, SAI2.SCKA, SAI2.FSA, SAI2.SDA, SAI2.SDB
mikroBUS: I2C8_SDA, SPI8_NSS, SPI8_MISO, SPI8_MOSI, SPI8_SCK, TIM3_CH2, LPUART1_RX, I2C8_SCL, LPUART1_TX, mkB_INT, mkB_RST, mkB_AN

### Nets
1V8: U53.5(VCC)
3V3: C69.1 CN5.1 CN5.17 CN25.7
5V: CN25.10 R289.2
5V_VIN: C62.2 CN5.2 CN5.4 R289.1
GND: C62.1 C69.2 CN5.6 CN5.9 CN5.14 CN5.20 CN5.25 CN5.30 CN5.34 CN5.39 CN25.8 CN25.9 R244.1 U53.2(VDD)
EXP_GPIO2: CN5.3 CN25.11 ; port GPIO.I2C8.SDA, port mkB.I2C8_SDA  [also labelled mkB.SDA]
EXP_GPIO3: CN5.5 CN25.12 ; port GPIO.I2C8.SCL, port mkB.I2C8_SCL  [also labelled mkB.SCL]
EXP_GPIO4: CN5.7 ; port GPIO.MCO1
EXP_GPIO5: CN5.29 ; port GPIO.TIM8.CH4
EXP_GPIO6: CN5.31 ; port GPIO.TIM12.CH2
EXP_GPIO7: CN5.26 ; port GPIO.PI.GPIO7
EXP_GPIO8: CN5.24 ; port GPIO.SPI3.NSS
EXP_GPIO9: CN5.21 ; port GPIO.SPI3.MISO
EXP_GPIO10: CN5.19 ; port GPIO.SPI3.MOSI
EXP_GPIO11: CN5.23 ; port GPIO.SPI3.SCK
EXP_GPIO12: CN5.32 ; port GPIO.TIM10.CH1
EXP_GPIO13: CN5.33 ; port GPIO.TIM8.CH1
EXP_GPIO14: CN5.8 ; port GPIO.USART6.TX
EXP_GPIO15: CN5.10 ; port GPIO.USART6.RX
EXP_GPIO16: CN5.36 ; port GPIO.USART6.CTS
EXP_GPIO17: CN5.11 ; port GPIO.USART6.RTS
EXP_GPIO18: CN5.12 ; port GPIO.SAI2.SCKA
EXP_GPIO19: CN5.35 ; port GPIO.SAI2.FSA
EXP_GPIO20: CN5.38 ; port GPIO.SAI2.SDA
EXP_GPIO21: CN5.40 ; port GPIO.SAI2.SDB
EXP_GPIO22: CN5.15 R94.2
EXP_GPIO23: CN5.16 ; port GPIO.SDMMC3.CMD
EXP_GPIO24: CN5.18 ; port GPIO.SDMMC3.D0
EXP_GPIO25: CN5.22 ; port GPIO.SDMMC3.D1
EXP_GPIO26: CN5.37 ; port GPIO.SDMMC3.D2
EXP_GPIO27: CN5.13 ; port GPIO.SDMMC3.D3
GPIO.SDMMC3_CK: R94.1 ; port GPIO.SDMMC3.CK
ID_SC: CN5.28 ; port GPIO.I2C2.SCL  [project net I2C2.SCL]
ID_SD: CN5.27 ; port GPIO.I2C2.SDA  [project net I2C2.SDA]
mkB.AN: U53.3(IN-) U53.4(OUT) ; port mkB.mkB_AN
mkB.CS: CN25.3 ; port mkB.SPI8_NSS
mkB.INT: CN25.15 ; port mkB.mkB_INT
mkB.MISO: CN25.5 ; port mkB.SPI8_MISO
mkB.MOSI: CN25.6 ; port mkB.SPI8_MOSI
mkB.PWM: CN25.16 ; port mkB.TIM3_CH2
mkB.RST: CN25.2 ; port mkB.mkB_RST
mkB.RX: CN25.14 ; port mkB.LPUART1_RX
mkB.SCK: CN25.4 ; port mkB.SPI8_SCK
mkB.TX: CN25.13 ; port mkB.LPUART1_TX
NetCN25_1: CN25.1 R243.1
NetR243_2: R243.2 R244.2 U53.1(IN+)

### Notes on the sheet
- mikroBUS connector
- ANA0
- PZ5
- PZ6
- PZ2
- PZ1
- PZ0
- PB15
- PZ9
- PZ8
- PZ7
- PZ4
- PZ3
- EXPANSION CONNECTOR

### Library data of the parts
C62 C69 = MCD-00006: Capacitor, MLCC, 100nF, 16V, X7R, +/-10%, 0402, T=0.5mm; Part_Preference: Recommended; Manufacturer: YAGEO; Manufacturer_Part_Number: CC0402KRX7R7BB104; Partial_Alternate_Internal_Part_Number: MCD-03299; Order_Code_RS: 9402047; Component_Country_Of_Origin: China; ShowFields: YES; ID: 2474
CN5 = MCD-00302: Header, 20x2, 2.54mm, VR, TH, T=5.84mm/2.54mm; Manufacturer_Part_Number: TSW-120-07-G-D; Manufacturer: SAMTEC; Part_Type: Connector; Part_Preference: Recommended; Partial_Alternate_Internal_Part_Number: MCD-04364; Order_Code_RS: 180-2456; Component_Country_Of_Origin: China, Costa Rica, Malaysia, USA, Vietnam; ShowFields: YES; ID: 2567
CN25 = MCD-03517: Socket , mikroBUS , 16 , SMD , Gray; Part_Type: Connector; Part_Preference: Recommended; Manufacturer: MIKROE; Component_Country_Of_Origin: Serbia; ShowFields: YES; ID: 5633
R94 = MCD-02978: Resistor, 22R, 0201, +/-1%, 1/20W; Manufacturer_Part_Number: RC0201FR-0722RL; Manufacturer: YAGEO; Part_Preference: Recommended; Order_Code_RS: 198-7593; ID: 5094; ShowFields: YES; Component_Country_Of_Origin: China
R243 = MCD-00483: Resistor, 470K, 0402, +/-1%, 1/16W; Part_Preference: Recommended; Manufacturer: YAGEO; Manufacturer_Part_Number: RC0402FR-07470KL; Component_Country_Of_Origin: China; ShowFields: YES; ID: 2797
R244 = MCD-00495: Resistor, 560K, 0402, +/-1%, 1/16W; Part_Preference: Recommended; Manufacturer: YAGEO; Manufacturer_Part_Number: RC0402FR-07560KL; Component_Country_Of_Origin: China; ShowFields: YES; ID: 2779
R289 = MCD-00052: Resistor,0R,0402,5%,1/16W; Manufacturer_Part_Number: RC0402JR-070RL; Manufacturer: YAGEO; Part_Preference: Recommended; Provided_By: SUBCO; Initial_Board_Reference: mb1274; Order_Code_RS: 9232516RL; Component_Country_Of_Origin: China; ID: 2540; ShowFields: YES
U53 = MCD-02043: Single,  rail to rail input/ouput 880Khz operational amplifiers; Part_Type: IC; Part_Preference: Recommended; Manufacturer: STMICROELECTRONICS; Manufacturer_HQ_COO: EU; Order_Code_RS: 189-2129; Component_Country_Of_Origin: Malaysia; ShowFields: YES; ID: 4143

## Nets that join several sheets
1V5_PCIE: USB_PCIe (6 pins), Power_PMIC (R69.2)
1V8: Video (C1.2 CN3.60), SDcard_eMMC (11 pins), Power_MPU (20 pins), Power_PMIC (LNK1.2 LNK3.2 R35.2), Expansion _&_mikroBUS_Connectors (U53.5)
3V3: Video (9 pins), MP257_18x18 (R224.2 R228.2), FDCAN (6 pins), Ethernet1 (L10.2 L14.2), Ethernet2 (L9.2 L15.2), Ethernet3 (L11.2 L13.2), Peripherals (R3.1 R4.1 R19.2 R20.2), QSPI_NOR (C175.2 R23.2 R33.2 U22.B4), USB_HUB (20 pins), USB_PCIe (15 pins), Power_PMIC (8 pins), Expansion _&_mikroBUS_Connectors (C69.1 CN5.1 CN5.17 CN25.7)
5V_STLK: STLINK_V3EC (7 pins), Power_PMIC (JP4.1)
5V_VIN: Video (R5.2 R18.1), FDCAN (C14.1 C100.1 U23.3 U31.3), USB_HUB (C143.2 C146.2 L12.1), USB_PCIe (C162.2 Q5.5 Q5.6), STLINK_V3EC (D2.1 R216.2), Power_PMIC (25 pins), Expansion _&_mikroBUS_Connectors (C62.2 CN5.2 CN5.4 R289.1)
GND: Video (64 pins), SDcard_eMMC (27 pins), MP257_18x18 (15 pins), FDCAN (20 pins), Ethernet1 (38 pins), Ethernet2 (38 pins), Ethernet3 (38 pins), Peripherals (19 pins), QSPI_NOR (C175.1 U22.B3), Power_MPU (107 pins), USB_HUB (42 pins), 2_DDR4_16bits (87 pins), USB_PCIe (65 pins), STLINK_V3EC (103 pins), Power_PMIC (84 pins), Expansion _&_mikroBUS_Connectors (14 pins)
VBAT: Peripherals (R30.2), Power_MPU (C87.2 D6.3 U27.P7)
VDD3V3_USB: Power_MPU (R286.1), Power_PMIC (C61.2 U26.13)
VDD_DDR: Power_MPU (16 pins), 2_DDR4_16bits (61 pins), Power_PMIC (5 pins)
VDD_EMMC: SDcard_eMMC (6 pins), Power_PMIC (C65.1 U26.16)
VDD_SDCARD: SDcard_eMMC (C6.2 CN1.4), Power_PMIC (C72.1 U26.4)
VDDA1V8_AON: MP257_18x18 (R70.1 U27.T7), Power_MPU (C234.2 U27.R7), Power_PMIC (R58.2)
VDDCORE: Power_MPU (20 pins), Power_PMIC (LNK2.2 LNK5.1 R36.2)
VDDCPU: Power_MPU (14 pins), Power_PMIC (LNK4.1 LNK6.1 R39.2)
VDDGPU: Power_MPU (12 pins), Power_PMIC (LNK7.2 LNK10.1 R45.2)
VDDIO: MP257_18x18 (10 pins), Peripherals (11 pins), Power_MPU (18 pins), USB_PCIe (R91.2 R223.2), STLINK_V3EC (LNK13.1), Power_PMIC (LNK11.2 LNK12.2 R53.2 U26.29)
VDDIO_SDCARD: SDcard_eMMC (7 pins), Power_MPU (C195.2 U27.G10), Power_PMIC (C63.1 U26.2)
VPP_DDR: 2_DDR4_16bits (8 pins), Power_PMIC (C74.1 U26.7)
VREF_DDR: 2_DDR4_16bits (C49.2 C78.2 U28.M1 U29.M1), Power_PMIC (R52.2)
VTT_DDR: 2_DDR4_16bits (38 pins), Power_PMIC (C40.2 U26.44)
BOOT0: MP257_18x18 (U27.R4), Peripherals (SW1.8)
BOOT1: MP257_18x18 (U27.R3), Peripherals (SW1.7)
BOOT2: MP257_18x18 (U27.T2), Peripherals (SW1.6)
BOOT3: MP257_18x18 (U27.T1), Peripherals (SW1.5)
BUTTON.TAMP: MP257_18x18 (U27.M6), Peripherals (6 pins)
BUTTON.User1: MP257_18x18 (U27.E14), Peripherals (C12.2 R29.1)
BUTTON.User2: MP257_18x18 (U27.L5), Peripherals (C11.2 R28.1)
CAM_ENABLE: Video (CN4.18 U16.1), MP257_18x18 (U27.G5)
CAM_RESET: Video (CN4.17 U15.1), MP257_18x18 (U27.L6)
DISP.BLCTRL: Video (CN2.37 CN3.53 U2.1), MP257_18x18 (U27.H5)
DISP.DSI_INT: Video (CN3.4), MP257_18x18 (U27.D13)
DISP.LED_EN: Video (CN2.36 U4.1), MP257_18x18 (U27.H4)
DISP.LVDS_INT: Video (CN2.2 U1.1), MP257_18x18 (U27.G2)
DISP.RESET: Video (CN3.57 R2.1 R9.2), MP257_18x18 (U27.G4)
DISP.TE: Video (CN3.49), MP257_18x18 (U27.K7)
eMMC.SDMMC2_CK: SDcard_eMMC (R49.1 U24.M6), MP257_18x18 (U27.A20)
eMMC.SDMMC2_CMD: SDcard_eMMC (R37.1 U24.M5), MP257_18x18 (U27.F17)
eMMC.SDMMC2_D0: SDcard_eMMC (R44.1 U24.A3), MP257_18x18 (U27.B19)
eMMC.SDMMC2_D1: SDcard_eMMC (U24.A4), MP257_18x18 (U27.E17)
eMMC.SDMMC2_D2: SDcard_eMMC (U24.A5), MP257_18x18 (U27.C18)
eMMC.SDMMC2_D3: SDcard_eMMC (U24.B2), MP257_18x18 (U27.C19)
eMMC.SDMMC2_D4: SDcard_eMMC (U24.B3), MP257_18x18 (U27.A19)
eMMC.SDMMC2_D5: SDcard_eMMC (U24.B4), MP257_18x18 (U27.D18)
eMMC.SDMMC2_D6: SDcard_eMMC (U24.B5), MP257_18x18 (U27.E16)
eMMC.SDMMC2_D7: SDcard_eMMC (U24.B6), MP257_18x18 (U27.D17)
ETH1.CLK: MP257_18x18 (U27.W10), Ethernet1 (R197.1), Ethernet3 (R198.1)
ETH1.CLK125: MP257_18x18 (U27.AB12), Ethernet1 (R93.1)
ETH1.GTX_CLK: MP257_18x18 (U27.AA12), Ethernet1 (R162.1)
ETH1.MDC: MP257_18x18 (U27.V12), Ethernet1 (R202.1 U39.13), Ethernet3 (R203.1 U40.13)
ETH1.MDINT: MP257_18x18 (U27.U12), Ethernet1 (R316.1 U39.31)
ETH1.MDIO: MP257_18x18 (U27.V10), Ethernet1 (R192.1 U39.14), Ethernet3 (R193.1 U40.14)
ETH1.NRST: MP257_18x18 (R206.1 U27.M1), Ethernet1 (U39.12), Ethernet3 (U40.12)
ETH1.RX_CLK: MP257_18x18 (U27.U10), Ethernet1 (R115.1 R141.1 R302.2)
ETH1.RX_CTL: MP257_18x18 (U27.W12), Ethernet1 (R116.1 R142.1 R301.2)
ETH1.RXD0: MP257_18x18 (U27.W11), Ethernet1 (R117.1 R143.1 R296.2)
ETH1.RXD1: MP257_18x18 (U27.Y11), Ethernet1 (R108.1 R144.1 R295.2)
ETH1.RXD2: MP257_18x18 (U27.AA11), Ethernet1 (R145.1 R294.2)
ETH1.RXD3: MP257_18x18 (U27.AB11), Ethernet1 (R118.1 R146.1 R300.2)
ETH1.TX_CTL: MP257_18x18 (U27.Y12), Ethernet1 (R165.1)
ETH1.TXD0: MP257_18x18 (U27.T10), Ethernet1 (R168.1)
ETH1.TXD1: MP257_18x18 (U27.V11), Ethernet1 (R174.1)
ETH1.TXD2: MP257_18x18 (U27.U11), Ethernet1 (R179.1)
ETH1.TXD3: MP257_18x18 (U27.T11), Ethernet1 (R186.1)
ETH2.CLK: MP257_18x18 (U27.Y10), Ethernet2 (R196.1)
ETH2.CLK125: MP257_18x18 (U27.AA8), Ethernet2 (R176.1)
ETH2.GTX_CLK: MP257_18x18 (U27.T9), Ethernet2 (R161.1)
ETH2.MDC: MP257_18x18 (U27.AA10), Ethernet2 (R195.1 U38.13)
ETH2.MDINT: MP257_18x18 (U27.Y9), Ethernet2 (R318.1 U38.31)
ETH2.MDIO: MP257_18x18 (U27.U9), Ethernet2 (R191.1 U38.14)
ETH2.NRST: MP257_18x18 (R205.1 U27.H2), Ethernet2 (U38.12)
ETH2.RX_CLK: MP257_18x18 (U27.AB8), Ethernet2 (R109.1 R135.1 R305.2)
ETH2.RX_CTL: MP257_18x18 (U27.W9), Ethernet2 (R110.1 R136.1 R304.2)
ETH2.RXD0: MP257_18x18 (U27.W7), Ethernet2 (R111.1 R137.1 R293.2)
ETH2.RXD1: MP257_18x18 (U27.Y7), Ethernet2 (R112.1 R138.1 R292.2)
ETH2.RXD2: MP257_18x18 (U27.AA7), Ethernet2 (R113.2 R139.1)
ETH2.RXD3: MP257_18x18 (U27.AB7), Ethernet2 (R114.1 R140.1 R303.2)
ETH2.TX_CTL: MP257_18x18 (U27.V9), Ethernet2 (R164.1)
ETH2.TXD0: MP257_18x18 (U27.Y8), Ethernet2 (R167.1)
ETH2.TXD1: MP257_18x18 (U27.V8), Ethernet2 (R173.1)
ETH2.TXD2: MP257_18x18 (U27.U8), Ethernet2 (R178.1)
ETH2.TXD3: MP257_18x18 (U27.T8), Ethernet2 (R185.1)
ETH3.GTX_CLK: MP257_18x18 (U27.V13), Ethernet3 (R163.1)
ETH3.MDINT: MP257_18x18 (U27.V15), Ethernet3 (R314.1 U40.31)
ETH3.RX_CLK: MP257_18x18 (U27.Y13), Ethernet3 (R119.1 R147.1 R299.2)
ETH3.RX_CTL: MP257_18x18 (U27.W13), Ethernet3 (R120.1 R148.1 R298.2)
ETH3.RXD0: MP257_18x18 (U27.T12), Ethernet3 (R121.1 R149.1 R307.2)
ETH3.RXD1: MP257_18x18 (U27.U13), Ethernet3 (R122.1 R150.1 R306.2)
ETH3.RXD2: MP257_18x18 (U27.T13), Ethernet3 (R123.2 R151.1)
ETH3.RXD3: MP257_18x18 (U27.U14), Ethernet3 (R124.1 R152.1 R297.2)
ETH3.TX_CTL: MP257_18x18 (U27.T14), Ethernet3 (R166.1)
ETH3.TXD0: MP257_18x18 (U27.V14), Ethernet3 (R169.1)
ETH3.TXD1: MP257_18x18 (U27.Y14), Ethernet3 (R175.1)
ETH3.TXD2: MP257_18x18 (U27.AA14), Ethernet3 (R180.1)
ETH3.TXD3: MP257_18x18 (U27.W14), Ethernet3 (R187.1)
EXP_GPIO2: MP257_18x18 (R246.1 U27.N4), USB_PCIe (R291.2), Expansion _&_mikroBUS_Connectors (CN5.3 CN25.11)
EXP_GPIO3: MP257_18x18 (R245.1 U27.R5), USB_PCIe (R290.2), Expansion _&_mikroBUS_Connectors (CN5.5 CN25.12)
EXP_GPIO4: MP257_18x18 (TP11.1 U27.Y6), Expansion _&_mikroBUS_Connectors (CN5.7)
EXP_GPIO5: MP257_18x18 (U27.W3), Expansion _&_mikroBUS_Connectors (CN5.29)
EXP_GPIO6: MP257_18x18 (U27.B12), Expansion _&_mikroBUS_Connectors (CN5.31)
EXP_GPIO7: MP257_18x18 (U27.Y3), Expansion _&_mikroBUS_Connectors (CN5.26)
EXP_GPIO8: MP257_18x18 (U27.D11), Expansion _&_mikroBUS_Connectors (CN5.24)
EXP_GPIO9: MP257_18x18 (U27.A11), Expansion _&_mikroBUS_Connectors (CN5.21)
EXP_GPIO10: MP257_18x18 (U27.G11), Expansion _&_mikroBUS_Connectors (CN5.19)
EXP_GPIO11: MP257_18x18 (U27.D12), Expansion _&_mikroBUS_Connectors (CN5.23)
EXP_GPIO12: MP257_18x18 (U27.A12), Expansion _&_mikroBUS_Connectors (CN5.32)
EXP_GPIO13: MP257_18x18 (U27.V4), Expansion _&_mikroBUS_Connectors (CN5.33)
EXP_GPIO14: MP257_18x18 (U27.L4), Expansion _&_mikroBUS_Connectors (CN5.8)
EXP_GPIO15: MP257_18x18 (U27.H1), Expansion _&_mikroBUS_Connectors (CN5.10)
EXP_GPIO16: MP257_18x18 (U27.L7), Expansion _&_mikroBUS_Connectors (CN5.36)
EXP_GPIO17: MP257_18x18 (U27.L1), Expansion _&_mikroBUS_Connectors (CN5.11)
EXP_GPIO18: MP257_18x18 (U27.M5), Expansion _&_mikroBUS_Connectors (CN5.12)
EXP_GPIO19: MP257_18x18 (U27.AA3), Expansion _&_mikroBUS_Connectors (CN5.35)
EXP_GPIO20: MP257_18x18 (U27.L2), Expansion _&_mikroBUS_Connectors (CN5.38)
EXP_GPIO21: MP257_18x18 (U27.AB3), Expansion _&_mikroBUS_Connectors (CN5.40)
EXP_GPIO23: MP257_18x18 (U27.A21), Expansion _&_mikroBUS_Connectors (CN5.16)
EXP_GPIO24: MP257_18x18 (U27.C20), Expansion _&_mikroBUS_Connectors (CN5.18)
EXP_GPIO25: MP257_18x18 (U27.B21), Expansion _&_mikroBUS_Connectors (CN5.22)
EXP_GPIO26: MP257_18x18 (U27.B20), Expansion _&_mikroBUS_Connectors (CN5.37)
EXP_GPIO27: MP257_18x18 (U27.E18), Expansion _&_mikroBUS_Connectors (CN5.13)
FDCAN1.RX: MP257_18x18 (U27.J3), FDCAN (U23.4)
FDCAN1.STBY: MP257_18x18 (U27.M4), FDCAN (R34.1 U23.8)
FDCAN1.TX: MP257_18x18 (U27.J4), FDCAN (U23.1)
FDCAN3.RX: MP257_18x18 (U27.G1), FDCAN (U31.4)
FDCAN3.STBY: MP257_18x18 (U27.K2), FDCAN (R81.1 U31.8)
FDCAN3.TX: MP257_18x18 (U27.L3), FDCAN (U31.1)
GPIO.SDMMC3_CK: MP257_18x18 (U27.D19), Expansion _&_mikroBUS_Connectors (R94.1)
HDMI_CEC: Video (CN3.47), MP257_18x18 (U27.F12)
HDMI_I2S2.CK: Video (CN3.35), MP257_18x18 (U27.C11)
HDMI_I2S2.WS: Video (CN3.37), MP257_18x18 (U27.G13)
HDMI_I2S2_SDO: Video (CN3.39), MP257_18x18 (U27.E12)
I2C1.SCL: MP257_18x18 (R224.1 U27.K5), USB_PCIe (U50.18)
I2C1.SDA: MP257_18x18 (R228.1 U27.H6), USB_PCIe (U50.17)
I2C2.SCL: Video (CN2.7 CN3.44 CN4.20), MP257_18x18 (R32.1 U27.B11), Expansion _&_mikroBUS_Connectors (CN5.28)
I2C2.SDA: Video (CN2.8 CN3.40 CN4.21), MP257_18x18 (R31.1 U27.D10), Expansion _&_mikroBUS_Connectors (CN5.27)
I2C7.SCL: MP257_18x18 (R261.1 U27.F16), Power_PMIC (U26.33)
I2C7.SDA: MP257_18x18 (R260.1 U27.G15), Power_PMIC (U26.34)
IMU_INT1: Video (CN4.14 U13.1), MP257_18x18 (U27.J6)
IMU_INT2: Video (CN4.15 U14.1), MP257_18x18 (U27.K6)
JTCK_SWCLK: MP257_18x18 (CN22.4 CN22.7 U27.AA1), STLINK_V3EC (R153.2)
JTDI: MP257_18x18 (CN22.8 U27.AB2), STLINK_V3EC (R207.2)
JTDO_SWDO: MP257_18x18 (CN22.6 U27.W1), STLINK_V3EC (R129.2)
JTMS_SWDIO: MP257_18x18 (CN22.2 U27.Y1), STLINK_V3EC (R209.2)
LED1: MP257_18x18 (U27.AB15), Peripherals (LD1.2)
LED2: MP257_18x18 (U27.C13), Peripherals (Q3.1 R17.2)
LED3: MP257_18x18 (U27.U5), Peripherals (Q2.1 R16.2)
LED4: MP257_18x18 (U27.W2), Peripherals (Q1.1 R8.2)
mkB.AN: MP257_18x18 (U27.V5), Expansion _&_mikroBUS_Connectors (U53.3 U53.4)
mkB.CS: MP257_18x18 (U27.R6), Expansion _&_mikroBUS_Connectors (CN25.3)
mkB.INT: MP257_18x18 (U27.N3), Expansion _&_mikroBUS_Connectors (CN25.15)
mkB.MISO: MP257_18x18 (U27.N6), Expansion _&_mikroBUS_Connectors (CN25.5)
mkB.MOSI: MP257_18x18 (U27.N5), Expansion _&_mikroBUS_Connectors (CN25.6)
mkB.PWM: MP257_18x18 (U27.AB4), Expansion _&_mikroBUS_Connectors (CN25.16)
mkB.RST: MP257_18x18 (U27.P5), Expansion _&_mikroBUS_Connectors (CN25.2)
mkB.RX: MP257_18x18 (U27.P3), Expansion _&_mikroBUS_Connectors (CN25.14)
mkB.SCK: MP257_18x18 (U27.P4), Expansion _&_mikroBUS_Connectors (CN25.4)
mkB.TX: MP257_18x18 (U27.P2), Expansion _&_mikroBUS_Connectors (CN25.13)
NRST: MP257_18x18 (C336.2 CN22.10 U27.U3), Peripherals (B1.1 B1.2 R7.1 U10.1), QSPI_NOR (R21.1), STLINK_V3EC (R212.2), Power_PMIC (R38.1)
NRSTC1MS: SDcard_eMMC (D5.2), MP257_18x18 (R27.1 R272.1 U27.T3), QSPI_NOR (R22.1), Power_PMIC (R59.1)
PA0_WKUP: MP257_18x18 (U27.Y2), Power_PMIC (U26.32)
PCIE.CLKREQN: MP257_18x18 (U27.U15), USB_PCIe (CN13.7 Q4.1 R91.1)
PCIE.NWAKE: MP257_18x18 (U27.AA15), USB_PCIe (CN13.1)
PCIE.RSTN: MP257_18x18 (R96.1 U27.M2), USB_PCIe (CN13.22)
PCIE.USB_N: USB_HUB (U34.1), USB_PCIe (CN13.36)
PCIE.USB_P: USB_HUB (U34.2), USB_PCIe (CN13.38)
PWR_CPU_ON: MP257_18x18 (R272.2 U27.T6), Power_PMIC (R60.1)
PWR_ON: MP257_18x18 (R74.2 U27.T5), Power_PMIC (R61.1)
QSPI1.CLK: MP257_18x18 (U27.D14), QSPI_NOR (U22.B2)
QSPI1.IO0: MP257_18x18 (U27.C14), QSPI_NOR (U22.D3)
QSPI1.IO1: MP257_18x18 (U27.B15), QSPI_NOR (U22.D2)
QSPI1.IO2: MP257_18x18 (U27.A15), QSPI_NOR (U22.C4)
QSPI1.IO3: MP257_18x18 (U27.D15), QSPI_NOR (U22.D4)
QSPI1.NCS1: MP257_18x18 (U27.C15), QSPI_NOR (R33.1 U22.C2)
SD.SDMMC1_CK: SDcard_eMMC (R247.1), MP257_18x18 (U27.D16)
SD.SDMMC1_CMD: SDcard_eMMC (CN1.3 R12.1 U8.4 U8.7), MP257_18x18 (U27.C16)
SD.SDMMC1_D0: SDcard_eMMC (CN1.7 R14.1 U9.2 U9.9), MP257_18x18 (U27.B17)
SD.SDMMC1_D1: SDcard_eMMC (CN1.8 R15.1 U9.4 U9.7), MP257_18x18 (U27.C17)
SD.SDMMC1_D2: SDcard_eMMC (CN1.1 R10.1 U8.1 U8.10), MP257_18x18 (U27.A16)
SD.SDMMC1_D3: SDcard_eMMC (CN1.2 R11.1 U8.2 U8.9), MP257_18x18 (U27.B16)
SD.uSD_DETECT: SDcard_eMMC (R6.1), MP257_18x18 (U27.B13)
TCPP_EN: MP257_18x18 (U27.Y4), USB_PCIe (R326.1)
TCPP_INTN: MP257_18x18 (U27.W6), USB_PCIe (U50.19)
TOF_INT: Video (CN4.12 U12.1), MP257_18x18 (U27.J5)
TOF_LPn: Video (CN4.11 U11.1), MP257_18x18 (U27.K4)
USBH_N: USB_HUB (U34.30), USB_PCIe (U27.AB16)
USBH_P: USB_HUB (U34.31), USB_PCIe (U27.AA16)
VBUS_DIV: MP257_18x18 (TP35.1 U27.AA6), USB_PCIe (R219.1 R220.2)
WAKEUPn: MP257_18x18 (U27.P6), Power_PMIC (R46.1)

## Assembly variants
MP257F_X: not fitted C91 C151 C165 C166 CN14 D5 R22 R27 R30 R56 R70 R72 R74 R77 R78 R93 R97 R99 R100 R108 R109 R110 R111 R112 R115 R117 R118 R119 R121 R122 R196 R197 R198 R223 R227 R229 R288 R290 R291 R297 R298 R301 R303 R325 R328 U49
